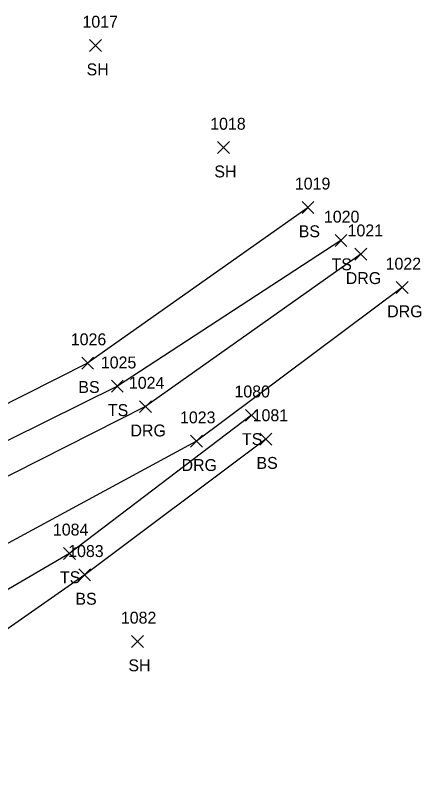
# Model space of a CAD drawing. Extents: x 1520648 to 1523413, y 732854 to 735518.
# Drawn here: x 1522925 to 1522993.1, y 734648.2 to 734778.9 of the extents above; entities that cross this region are included whole.
import ezdxf

# ---------------------------------------------------------------- set-up
doc = ezdxf.new("R2010")
doc.units = 0
for name, color, linetype in [('L_A', 7, 'Continuous'), ('L_I', 7, 'Continuous'), ('L_TIC', 7, 'Continuous'), ('LELB', 7, 'Continuous'), ('R_A', 7, 'Continuous'), ('R_I', 7, 'Continuous'), ('R_TIC', 7, 'Continuous'), ('RDG', 7, 'Continuous')]:
    doc.layers.add(name, color=color, linetype=linetype)

msp = doc.modelspace()

# ---------------------------------------------------------------- linework, layer by layer
at = {"layer": 'L_TIC'}
for points in [[(1522937.43, 734772.86), (1522939.43, 734774.86)], [(1522939.43, 734772.86), (1522937.43, 734774.86)], [(1522958.87, 734755.73), (1522960.87, 734757.73)], [(1522960.87, 734755.73), (1522958.87, 734757.73)], [(1522973.07, 734745.69), (1522975.07, 734747.69)], [(1522975.07, 734745.69), (1522973.07, 734747.69)], [(1522978.6, 734740.14), (1522980.6, 734742.14)], [(1522980.6, 734740.14), (1522978.6, 734742.14)], [(1522936.1, 734719.55), (1522938.1, 734721.55)], [(1522938.1, 734719.55), (1522936.1, 734721.55)], [(1522941.08, 734715.67), (1522943.08, 734717.67)], [(1522943.08, 734715.67), (1522941.08, 734717.67)], [(1522963.59, 734710.8), (1522965.59, 734712.8)], [(1522965.59, 734710.8), (1522963.59, 734712.8)], [(1522965.98, 734706.81), (1522967.98, 734708.81)], [(1522967.98, 734706.81), (1522965.98, 734708.81)], [(1522933.04, 734687.62), (1522935.04, 734689.62)], [(1522935.04, 734687.62), (1522933.04, 734689.62)], [(1522935.6, 734684.01), (1522937.6, 734686.01)], [(1522937.6, 734684.01), (1522935.6, 734686.01)], [(1522944.44, 734672.83), (1522946.44, 734674.83)], [(1522946.44, 734672.83), (1522944.44, 734674.83)]]:
    msp.add_lwpolyline(points, dxfattribs=at)
at = {"layer": 'LELB'}
for points in [[(1522974.07, 734746.69), (1522937.1, 734720.55), (1522884.55, 734694.03), (1522866.08, 734693.27), (1522844.2, 734708.73), (1522844.46, 734714.37)], [(1522979.6, 734741.14), (1522942.08, 734716.67), (1522887.65, 734689.74), (1522865.97, 734688.66), (1522839.74, 734700.93), (1522829.98, 734708.17)], [(1522964.59, 734711.8), (1522934.04, 734688.62), (1522903.57, 734670.84), (1522893.31, 734656.71), (1522881.6, 734654.9), (1522856.07, 734664.39), (1522835.94, 734674.96), (1522815.99, 734683.04), (1522809.93, 734682.93), (1522803.99, 734678.79), (1522800.17, 734672.61), (1522781.12, 734647.81), (1522752.35, 734609.03), (1522722.77, 734569.04), (1522693.92, 734527.21), (1522653.61, 734471.8)], [(1522966.98, 734707.81), (1522936.6, 734685.01), (1522907.63, 734664.77), (1522896.44, 734650.45), (1522881.66, 734649.85), (1522854.58, 734659.5), (1522833, 734670.65), (1522815.02, 734680.19), (1522811.05, 734676.42), (1522816.52, 734667.94), (1522809.83, 734658.42), (1522800.06, 734661.2), (1522785.93, 734645.15), (1522763.72, 734601.03), (1522733.15, 734561.61), (1522704.24, 734521.86), (1522660.18, 734466.65)]]:
    msp.add_lwpolyline(points, dxfattribs=at)
at = {"layer": 'R_TIC'}
for points in [[(1522981.91, 734737.83), (1522983.91, 734739.83)], [(1522983.91, 734737.83), (1522981.91, 734739.83)], [(1522988.86, 734732.25), (1522990.86, 734734.25)], [(1522990.86, 734732.25), (1522988.86, 734734.25)], [(1522945.8, 734712.25), (1522947.8, 734714.25)], [(1522947.8, 734712.25), (1522945.8, 734714.25)], [(1522954.36, 734706.45), (1522956.36, 734708.45)], [(1522956.36, 734706.45), (1522954.36, 734708.45)]]:
    msp.add_lwpolyline(points, dxfattribs=at)
at = {"layer": 'RDG'}
for points in [[(1522982.91, 734738.83), (1522946.8, 734713.25), (1522889.18, 734684.15), (1522864.63, 734684.64), (1522837.53, 734694.99)], [(1522989.86, 734733.25), (1522955.36, 734707.45), (1522893.47, 734673.95), (1522863.96, 734672.67), (1522847.82, 734676.15), (1522830.89, 734683.99)]]:
    msp.add_lwpolyline(points, dxfattribs=at)

# ---------------------------------------------------------------- texts
at = {"layer": 'L_A'}
for s, p in [('SH', (1522936.92, 734768.86)), ('SH', (1522958.35, 734751.73)), ('BS', (1522972.51, 734741.69)), ('TS', (1522978.01, 734736.14)), ('BS', (1522935.54, 734715.55)), ('TS', (1522940.49, 734711.67)), ('TS', (1522962.99, 734706.8)), ('BS', (1522965.42, 734702.81)), ('TS', (1522932.45, 734683.62)), ('BS', (1522935.04, 734680.01)), ('SH', (1522943.93, 734668.83))]:
    msp.add_text(s, height=2, dxfattribs=at).set_placement(p)
at = {"layer": 'L_I'}
for s, p in [('1017', (1522936.23, 734776.86)), ('1018', (1522957.66, 734759.73)), ('1019', (1522971.86, 734749.69)), ('1020', (1522976.74, 734744.14)), ('1026', (1522934.27, 734723.55)), ('1025', (1522939.31, 734719.67)), ('1080', (1522961.73, 734714.8)), ('1081', (1522964.78, 734710.81)), ('1084', (1522931.27, 734691.62)), ('1083', (1522933.83, 734688.01)), ('1082', (1522942.67, 734676.83))]:
    msp.add_text(s, height=2, dxfattribs=at).set_placement(p)
at = {"layer": 'R_A'}
for p in [(1522980.4, 734733.83), (1522987.35, 734728.25), (1522944.28, 734708.25), (1522952.85, 734702.45)]:
    msp.add_text('DRG', height=2, dxfattribs=at).set_placement(p)
at = {"layer": 'R_I'}
for s, p in [('1021', (1522980.71, 734741.83)), ('1022', (1522987.09, 734736.25)), ('1024', (1522944.02, 734716.25)), ('1023', (1522952.59, 734710.45))]:
    msp.add_text(s, height=2, dxfattribs=at).set_placement(p)

doc.saveas('drawing.dxf')
